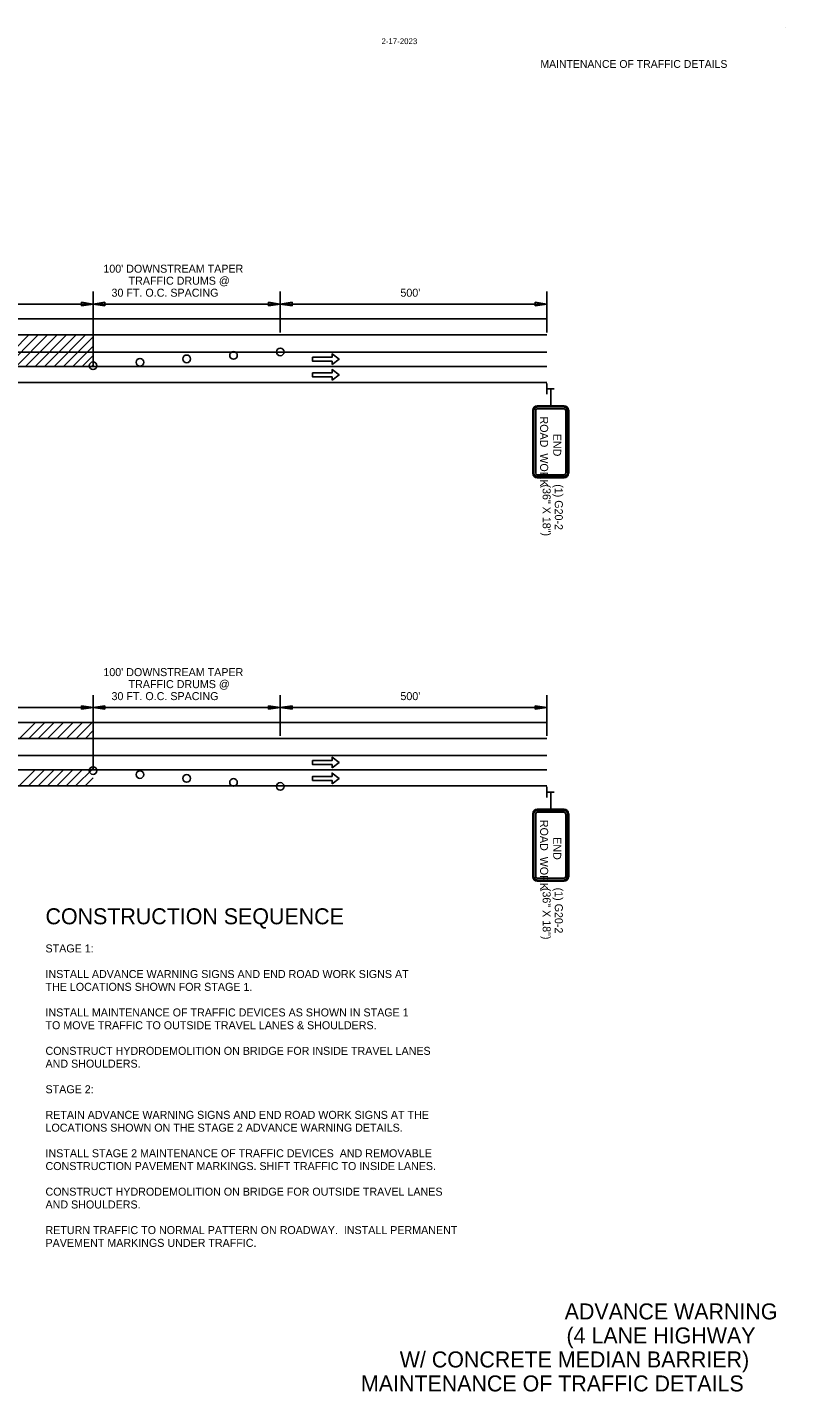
# Model space of a CAD drawing. Extents: x 1930579 to 1937984, y 596452 to 597630.
# Drawn here: x 1937415 to 1937984, y 596607 to 597630 of the extents above; entities that cross this region are included whole.
import ezdxf

# ---------------------------------------------------------------- set-up
doc = ezdxf.new("R2010")
doc.units = 0
for name, color, linetype in [('B_StampSCR', 7, 'Continuous'), ('Default', 7, 'Continuous'), ('P_TC_Signs_Temporary', 7, 'Continuous'), ('R_Border', 7, 'Continuous'), ('R_Border Prem', 7, 'Continuous'), ('R_Striping', 7, 'Continuous')]:
    doc.layers.add(name, color=color, linetype=linetype)

msp = doc.modelspace()

# ---------------------------------------------------------------- linework, layer by layer
at = {"layer": 'B_StampSCR'}
msp.add_line((1937804.9, 597386.4), (1936452.7, 597386.4), dxfattribs=at)
at = {"layer": 'Default'}
for p, q in [((1937464.5, 597422.4), (1937240, 597422.4)), ((1937455.7, 597421.1), (1937455.7, 597423.7)), ((1937455.7, 597423.7), (1937464.5, 597422.4)), ((1937464.5, 597422.4), (1937455.7, 597421.1)), ((1937464.5, 597431.7), (1937464.5, 597375.6)), ((1937473.4, 597423.7), (1937464.5, 597422.4)), ((1937604.9, 597422.4), (1937464.5, 597422.4)), ((1937464.5, 597422.4), (1937473.4, 597421.1)), ((1937473.4, 597421.1), (1937473.4, 597423.7)), ((1937596, 597421.1), (1937596, 597423.7)), ((1937596, 597423.7), (1937604.9, 597422.4)), ((1937604.9, 597422.4), (1937596, 597421.1)), ((1937604.9, 597431.7), (1937604.9, 597401)), ((1937613.7, 597423.7), (1937604.9, 597422.4)), ((1937804.9, 597422.4), (1937604.9, 597422.4)), ((1937604.9, 597422.4), (1937613.7, 597421.1)), ((1937613.7, 597421.1), (1937613.7, 597423.7)), ((1937796, 597421.1), (1937796, 597423.7)), ((1937796, 597423.7), (1937804.9, 597422.4)), ((1937804.9, 597422.4), (1937796, 597421.1)), ((1937804.9, 597431.7), (1937804.9, 597401)), ((1937804.9, 597411.2), (1936452.7, 597411.2)), ((1937804.9, 597399.2), (1936452.7, 597399.2)), ((1937804.9, 597399.2), (1936452.7, 597399.2)), ((1937392.7, 597375.6), (1937416.3, 597399.2)), ((1937399.8, 597375.6), (1937423.4, 597399.2)), ((1937406.9, 597375.6), (1937430.4, 597399.2)), ((1937413.9, 597375.6), (1937437.5, 597399.2)), ((1937421, 597375.6), (1937444.6, 597399.2)), ((1937428.1, 597375.6), (1937451.7, 597399.2)), ((1937435.2, 597375.6), (1937458.7, 597399.2)), ((1937442.2, 597375.6), (1937464.5, 597397.9)), ((1937449.3, 597375.6), (1937464.5, 597390.8)), ((1937456.4, 597375.6), (1937464.5, 597383.8)), ((1937804.9, 597375.6), (1936452.7, 597375.6)), ((1937463.4, 597375.6), (1937464.5, 597376.7)), ((1937463.4, 597375.6), (1937464.5, 597376.7)), ((1937804.9, 597363.6), (1936452.7, 597363.6)), ((1937804.9, 597354.9), (1937804.9, 597362.9)), ((1937805, 597358.9), (1937810.4, 597358.9)), ((1937464.5, 597129.2), (1937464.5, 597073.1)), ((1937604.9, 597129.2), (1937604.9, 597098.5)), ((1937804.9, 597129.2), (1937804.9, 597098.5)), ((1937464.5, 597119.9), (1937240, 597119.9)), ((1937455.7, 597118.6), (1937455.7, 597121.2)), ((1937455.7, 597121.2), (1937464.5, 597119.9)), ((1937464.5, 597119.9), (1937455.7, 597118.6)), ((1937473.4, 597121.2), (1937464.5, 597119.9)), ((1937604.9, 597119.9), (1937464.5, 597119.9)), ((1937464.5, 597119.9), (1937473.4, 597118.6)), ((1937473.4, 597118.6), (1937473.4, 597121.2)), ((1937596, 597118.6), (1937596, 597121.2)), ((1937596, 597121.2), (1937604.9, 597119.9)), ((1937604.9, 597119.9), (1937596, 597118.6)), ((1937613.7, 597121.2), (1937604.9, 597119.9)), ((1937804.9, 597119.9), (1937604.9, 597119.9)), ((1937604.9, 597119.9), (1937613.7, 597118.6)), ((1937613.7, 597118.6), (1937613.7, 597121.2)), ((1937796, 597118.6), (1937796, 597121.2)), ((1937796, 597121.2), (1937804.9, 597119.9)), ((1937804.9, 597119.9), (1937796, 597118.6)), ((1937804.9, 597108.7), (1936452.7, 597108.7)), ((1937409.2, 597096.7), (1937421.2, 597108.7)), ((1937416.3, 597096.7), (1937428.3, 597108.7)), ((1937423.4, 597096.7), (1937435.4, 597108.7)), ((1937430.4, 597096.7), (1937442.4, 597108.7)), ((1937437.5, 597096.7), (1937449.5, 597108.7)), ((1937444.6, 597096.7), (1937456.6, 597108.7)), ((1937451.7, 597096.7), (1937463.7, 597108.7)), ((1937804.9, 597096.7), (1936452.7, 597096.7)), ((1937458.7, 597096.7), (1937464.5, 597102.5)), ((1937804.9, 597083.8), (1936452.7, 597083.8)), ((1937451.4, 597061.1), (1937464.5, 597074.2)), ((1937463.4, 597073.1), (1937464.5, 597074.2)), ((1937804.9, 597073.1), (1936452.7, 597073.1)), ((1937409, 597061.1), (1937421, 597073.1)), ((1937416.1, 597061.1), (1937428.1, 597073.1)), ((1937423.2, 597061.1), (1937435.2, 597073.1)), ((1937430.2, 597061.1), (1937442.2, 597073.1)), ((1937437.3, 597061.1), (1937449.3, 597073.1)), ((1937444.4, 597061.1), (1937456.4, 597073.1)), ((1937458.5, 597061.1), (1937464.5, 597067.1)), ((1937804.9, 597061.1), (1936452.7, 597061.1)), ((1937804.9, 597052.4), (1937804.9, 597060.4)), ((1937805, 597056.4), (1937810.4, 597056.4))]:
    msp.add_line(p, q, dxfattribs=at)
for centre in [(1937499.6, 597378.7), (1937534.7, 597381.3), (1937569.8, 597383.9), (1937604.9, 597386.5), (1937464.5, 597376.1), (1937464.5, 597072.6), (1937499.6, 597069.6), (1937534.7, 597066.7), (1937569.8, 597063.7), (1937604.9, 597060.7)]:
    msp.add_circle(centre, 2.87, dxfattribs=at)
at = {"layer": 'P_TC_Signs_Temporary'}
for p, q in [((1937794.2, 597342.7), (1937794.2, 597295.5)), ((1937795.1, 597342.7), (1937795.1, 597295.5)), ((1937796.5, 597342.7), (1937796.5, 597295.5)), ((1937817.8, 597346.1), (1937797.6, 597346.1)), ((1937817.8, 597345.2), (1937797.6, 597345.2)), ((1937817.8, 597343.9), (1937797.6, 597343.9)), ((1937819, 597295.5), (1937819, 597342.7)), ((1937820.3, 597295.5), (1937820.3, 597342.7)), ((1937821.2, 597295.5), (1937821.2, 597342.7)), ((1937797.6, 597294.4), (1937817.8, 597294.4)), ((1937797.6, 597293.1), (1937817.8, 597293.1)), ((1937797.6, 597292.1), (1937817.8, 597292.1)), ((1937817.8, 597043.6), (1937797.6, 597043.6)), ((1937794.2, 597040.2), (1937794.2, 596993)), ((1937795.1, 597040.2), (1937795.1, 596993)), ((1937796.5, 597040.2), (1937796.5, 596993)), ((1937817.8, 597042.7), (1937797.6, 597042.7)), ((1937817.8, 597041.3), (1937797.6, 597041.3)), ((1937819, 596993), (1937819, 597040.2)), ((1937820.3, 596993), (1937820.3, 597040.2)), ((1937821.2, 596993), (1937821.2, 597040.2)), ((1937797.6, 596991.8), (1937817.8, 596991.8)), ((1937797.6, 596990.5), (1937817.8, 596990.5)), ((1937797.6, 596989.6), (1937817.8, 596989.6))]:
    msp.add_line(p, q, dxfattribs=at)
for centre, radius, start, end in [((1937797.6, 597342.7), 3.38, 90, 180), ((1937797.6, 597342.7), 2.44, 90, 180), ((1937797.6, 597342.7), 1.13, 90, 180), ((1937817.8, 597342.7), 3.37, 360, 90), ((1937817.8, 597342.7), 2.44, 360, 90), ((1937817.8, 597342.7), 1.13, 360, 90), ((1937797.6, 597295.5), 3.37, 180, 270), ((1937797.6, 597295.5), 2.44, 180, 270), ((1937797.6, 597295.5), 1.13, 180, 270), ((1937817.8, 597295.5), 2.44, 270, 360), ((1937817.8, 597295.5), 1.13, 270, 360), ((1937817.8, 597295.5), 3.38, 270, 360), ((1937797.6, 597040.2), 3.38, 90, 180), ((1937817.8, 597040.2), 3.37, 360, 90), ((1937797.6, 597040.2), 2.44, 90, 180), ((1937797.6, 597040.2), 1.13, 90, 180), ((1937817.8, 597040.2), 2.44, 360, 90), ((1937817.8, 597040.2), 1.13, 360, 90), ((1937797.6, 596993), 3.37, 180, 270), ((1937797.6, 596993), 2.44, 180, 270), ((1937797.6, 596993), 1.13, 180, 270), ((1937817.8, 596993), 2.44, 270, 360), ((1937817.8, 596993), 1.13, 270, 360), ((1937817.8, 596993), 3.38, 270, 360)]:
    msp.add_arc(centre, radius, start, end, dxfattribs=at)
at = {"layer": 'R_Border'}
for p, q in [((1937807.7, 597358.9), (1937807.7, 597346.1)), ((1937807.7, 597056.4), (1937807.7, 597043.6))]:
    msp.add_line(p, q, dxfattribs=at)
at = {"layer": 'R_Border Prem'}
msp.add_line((1937984, 597629.9), (1937984, 597629.9), dxfattribs=at)
at = {"layer": 'R_Striping'}
for points in [[(1937643.8, 597377), (1937649, 597381), (1937643.8, 597385), (1937643.8, 597382.5), (1937629.1, 597382.5), (1937629.1, 597379.5), (1937643.8, 597379.5)], [(1937643.8, 597365.2), (1937649, 597369.2), (1937643.8, 597373.2), (1937643.8, 597370.7), (1937629.1, 597370.7), (1937629.1, 597367.7), (1937643.8, 597367.7)], [(1937643.8, 597074.5), (1937649, 597078.5), (1937643.8, 597082.5), (1937643.8, 597080), (1937629.1, 597080), (1937629.1, 597077), (1937643.8, 597077)], [(1937643.8, 597062.7), (1937649, 597066.7), (1937643.8, 597070.7), (1937643.8, 597068.2), (1937629.1, 597068.2), (1937629.1, 597065.2), (1937643.8, 597065.2)]]:
    msp.add_lwpolyline(points, close=True, dxfattribs=at)

# ---------------------------------------------------------------- texts
at = {"layer": 'Default'}
for s, p in [("100' DOWNSTREAM TAPER", (1937472.2, 597445.9)), ('TRAFFIC DRUMS @ ', (1937491.1, 597436.9)), ('30 FT. O.C. SPACING', (1937478.3, 597427.9)), ("500'", (1937695, 597427.9)), ("100' DOWNSTREAM TAPER", (1937472.2, 597143.4)), ('TRAFFIC DRUMS @ ', (1937491.1, 597134.4)), ('30 FT. O.C. SPACING', (1937478.3, 597125.4)), ("500'", (1937695, 597125.4))]:
    msp.add_text(s, height=6, rotation=360, dxfattribs=at).set_placement(p)
at = {"layer": 'P_TC_Signs_Temporary'}
for s, p in [('ROAD  WORK', (1937799.8, 597338.1)), ('END', (1937809.6, 597325.1)), ('ROAD  WORK', (1937799.8, 597035.6)), ('END', (1937809.6, 597022.6))]:
    msp.add_text(s, height=6, rotation=270, dxfattribs=at).set_placement(p)
at = {"layer": 'R_Border'}
for s, height, rotation, p in [('(36" X 18")', 6, 270, (1937801.7, 597287.1)), ('(1) G20-2', 6, 270, (1937810.8, 597287.3)), ('(36" X 18")', 6, 270, (1937801.7, 596984.6)), ('(1) G20-2', 6, 270, (1937810.8, 596984.8)), ('CONSTRUCTION SEQUENCE', 12, 360, (1937428.8, 596957.3)), ('STAGE 1:', 6, 360, (1937428.8, 596936.2)), ('INSTALL ADVANCE WARNING SIGNS AND END ROAD WORK SIGNS AT', 6, 360, (1937428.8, 596917)), ('THE LOCATIONS SHOWN FOR STAGE 1.', 6, 360, (1937428.8, 596907.4)), ('INSTALL MAINTENANCE OF TRAFFIC DEVICES AS SHOWN IN STAGE 1', 6, 360, (1937428.8, 596888.2)), ('TO MOVE TRAFFIC TO OUTSIDE TRAVEL LANES & SHOULDERS.', 6, 360, (1937428.8, 596878.6)), ('CONSTRUCT HYDRODEMOLITION ON BRIDGE FOR INSIDE TRAVEL LANES', 6, 360, (1937428.8, 596859.4)), ('AND SHOULDERS.', 6, 360, (1937428.8, 596849.8)), ('STAGE 2:', 6, 360, (1937428.8, 596830.6)), ('RETAIN ADVANCE WARNING SIGNS AND END ROAD WORK SIGNS AT THE', 6, 360, (1937428.8, 596811.4)), ('LOCATIONS SHOWN ON THE STAGE 2 ADVANCE WARNING DETAILS.', 6, 360, (1937428.8, 596801.8)), ('INSTALL STAGE 2 MAINTENANCE OF TRAFFIC DEVICES  AND REMOVABLE', 6, 360, (1937428.8, 596782.6)), ('CONSTRUCTION PAVEMENT MARKINGS. SHIFT TRAFFIC TO INSIDE LANES.', 6, 360, (1937428.8, 596773)), ('CONSTRUCT HYDRODEMOLITION ON BRIDGE FOR OUTSIDE TRAVEL LANES', 6, 360, (1937428.8, 596753.8)), ('AND SHOULDERS.', 6, 360, (1937428.8, 596744.2)), ('RETURN TRAFFIC TO NORMAL PATTERN ON ROADWAY.  INSTALL PERMANENT', 6, 360, (1937428.8, 596725)), ('PAVEMENT MARKINGS UNDER TRAFFIC.', 6, 360, (1937428.8, 596715.4)), ('ADVANCE WARNING', 12, 360, (1937818.2, 596661)), (' (4 LANE HIGHWAY', 12, 360, (1937815.1, 596643)), ('W/ CONCRETE MEDIAN BARRIER)', 12, 360, (1937694.5, 596625)), ('MAINTENANCE OF TRAFFIC DETAILS ', 12, 360, (1937665.4, 596607))]:
    msp.add_text(s, height=height, rotation=rotation, dxfattribs=at).set_placement(p)
at = {"layer": 'R_Border Prem'}
msp.add_text('2-17-2023', height=4.4, dxfattribs=at).set_placement((1937680.8, 597617.3))
msp.add_text('MAINTENANCE OF TRAFFIC DETAILS', height=5.862, rotation=360, dxfattribs=at).set_placement((1937800, 597599.5))

doc.saveas('drawing.dxf')
